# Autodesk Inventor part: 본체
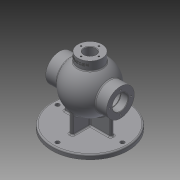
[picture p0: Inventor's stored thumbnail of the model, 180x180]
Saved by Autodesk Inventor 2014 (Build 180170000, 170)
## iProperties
Created: 2020-08
Part Number: 본체
Material: Generic
Document SubType Name: Modeling
Designer: kh
Density: 1 g/cm^3
Appearance: Default
Author: kh
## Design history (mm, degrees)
sketch "Sketch1"
  geometry: C1 r 85 at (0, 0); 1 further point
  constraints: 1 centre point, 1 coincident
  dimensions: "d0" = 170 diameter of C1
extrude "Extrusion1" new body sketch "Sketch1" distance "d1" = 10; taper "d2" = 0 deg
workplane "Work Plane1"
sketch "Sketch9"
  geometry: L1 (85, 10)-(-85, 10) reference; L2 (-85, 0)-(85, 0) reference; L3 (-76.651, 85)-(83.599, 85); L4 (-68, 116)-(-42.988, 116); L5 (42.988, 116)-(68, 116); L6 (-68, 102.5)-(-39.278, 102.5); L7 (39.278, 102.5)-(68, 102.5); L8 (68, 102.5)-(68, 116); L9 (-68, 102.5)-(-68, 116); L10 (0, 0)-(0, 85); A1 r 53 centre (0, 85) between (42.988, 116) and (-42.988, 116); A2 r 43 centre (0, 85) between (39.278, 102.5) and (-39.278, 102.5)
  constraints: 16 end point, 4 point on circle, 2 centre point, 2 coincident, 2 collinear, 2 parallel, 2 point on line, 2 vertical, 1 horizontal, 1 perpendicular, 1 other
  dimensions: "d72" = 85 distance from line of L2 L3.end; "d73" = 35 diameter of L6 L3; "d74" = 62 diameter of L4 L3; "d75" = 35 diameter of L7 L3; "d76" = 53 radius of A1; "d77" = 43 radius of A2; "d78" = 136 distance between parallel lines of L8 L9
revolve "Revolution2" sketch "Sketch9" stored, may be unused: angle "d79" = 90 deg
sketch "Sketch10"
  geometry: L1 (0, 0)-(0, 43); L2 (0, 43)-(-4, 43); L3 (-4, 43)-(-4, -43); L4 (-4, -43)-(4, -43); L5 (4, -43)-(4, 43); L6 (4, 43)-(0, 43); L7 (0, 0)-(-54, 0); L8 (-54, 0)-(-54, 4); L9 (-54, 4)-(50, 4); L10 (50, 4)-(50, -4); L11 (50, -4)-(-54, -4); L12 (-54, -4)-(-54, 0); C1 r 85 at (0, 0) reference; 1 further point
  constraints: 24 end point, 7 parallel, 2 perpendicular, 1 vertical
  dimensions: "d80" = 43 distance of L1.start L1.end; "d81" = 4 distance of L1.end L2.end; "d82" = 86 distance of L2.end L3.end; "d83" = 8 distance of L3.end L4.end; "d84" = 86 distance of L4.end L5.end; "d85" = 54 distance of L1.start L7.end; "d86" = 4 distance of L7.end L8.end; "d87" = 104 distance of L8.end L9.end; "d88" = 8 distance of L9.end L10.end; "d89" = 104 distance of L10.end L11.end
extrude "Extrusion7" join sketch "Sketch10" stored distance "d90" = 20; taper "d91" = 0 deg
workplane "Work Plane2"
sketch "Sketch11"
  geometry: C1 r 27 at (0, 0); 1 further point
  constraints: 1 centre point, 1 coincident
  dimensions: "d93" = 54 diameter of C1
extrude "Extrusion8" join sketch "Sketch11" stored distance "d94" = 20; taper "d95" = 0 deg
sketch "Sketch12" dims "d96" = 48
  geometry: L1 (0, 0)-(24, 0); C1 r 17.5 at (0, 0) reference; C2 r 31 at (0, 0) reference; 2 further points
  constraints: 2 coincident, 2 end point, 1 horizontal, 1 horizontal alignment, 2 other
hole "Hole1" sketch "Sketch12" at (24, 0) diameter "d97" = 3.459; stored, may be unused: countersink angle "d101" = 90 deg, drill point angle "d103" = 118 deg; dims "d98" = 12, "d99" = 4, "d100" = 2, "d102" = 15
pattern_circular "Circular Pattern1" dims angle "d105" = 360 deg
sketch "Sketch13" dims "d107" = 48
  geometry: L1 (0, 0)-(-24, 0); C1 r 31 at (0, 0) reference; C2 r 17.5 at (0, 0) reference; 2 further points
  constraints: 2 coincident, 2 end point, 1 horizontal, 1 horizontal alignment, 2 other
hole "Hole2" sketch "Sketch13" at (-24, 0) diameter "d108" = 3.459; stored, may be unused: countersink angle "d112" = 90 deg, drill point angle "d114" = 118 deg; dims "d109" = 12, "d110" = 4, "d111" = 2, "d113" = 15
pattern_circular "Circular Pattern2" dims angle "d116" = 360 deg
sketch "Sketch14"
  geometry: C1 r 27 at (0, 0) reference; C2 r 13 at (0, 0); 1 further point
  constraints: 1 centre point, 1 coincident
  dimensions: "d118" = 26 diameter of C2
extrude "Extrusion9" cut sketch "Sketch14" stored distance "d119" = 20; taper "d120" = 0 deg
sketch "Sketch15" dims "d121" = 40
  geometry: L1 (0, 0)-(0, 20); C1 r 13 at (0, 0) reference; C2 r 27 at (0, 0) reference; 2 further points
  constraints: 2 coincident, 2 end point, 1 vertical, 1 vertical alignment, 2 other
hole "Hole3" sketch "Sketch15" at (0, 20) diameter "d122" = 3.459; stored, may be unused: countersink angle "d126" = 90 deg, drill point angle "d128" = 118 deg; dims "d123" = 12, "d124" = 4, "d125" = 2, "d127" = 15
pattern_circular "Circular Pattern3" dims angle "d130" = 360 deg
sketch "Sketch16"
  geometry: L1 (0, 72.5)-(0, -72.5); L2 (-72.5, 0)-(72.5, 0); C1 r 85 at (0, 0) reference; A1 r 72.5 centre (0, 0) between (0, 72.5) and (0, -72.5); 7 further points
  constraints: 5 coincident, 4 end point, 4 midpoint, 4 point on circle, 1 centre point, 1 perpendicular, 1 vertical
  dimensions: "d132" = 145 diameter of A1
hole "Hole4" sketch "Sketch16" at (0, 72.5), (72.5, 0), (0, -72.5), (-72.5, 0) diameter "d133" = 9; stored, may be unused: countersink angle "d137" = 90 deg, drill point angle "d139" = 118 deg; dims "d134" = 12, "d135" = 4, "d136" = 2, "d138" = 15
sketch "Sketch17"
  geometry: L1 (-68, 67.5)-(-68, 102.5) reference; L2 (68, 67.5)-(68, 102.5) reference; L3 (-68, 85)-(68, 85); L4 (-39.278, 102.5)-(-68, 102.5) reference; L5 (-39.278, 67.5)-(-68, 67.5) reference; L6 (-52, 85)-(-52, 85); L7 (-52, 85)-(-52, 103.5); L8 (-52, 103.5)-(-50.25, 103.5); L9 (-50.25, 103.5)-(-50.25, 85); L10 (-52, 85)-(-50.25, 85); 1 further point
  constraints: 12 end point, 4 point on line, 3 perpendicular, 2 collinear, 2 midpoint
  dimensions: "d143" = 16 distance between parallel lines of L7 L1; "d144" = 37 diameter of L8 L3; "d145" = 1.75 distance of L7.end L8.end
revolve "Revolution3" sketch "Sketch17" stored, may be unused: angle "d146" = 90 deg
chamfer "Chamfer1" distance "d147" = 1; stored, may be unused: second distance "d148" = 2, angle "d149" = 45 deg
fillet "Fillet1" dims "d150" = 3
fillet "Fillet2" dims "d151" = 3
fillet "Fillet3" dims "d152" = 3
fillet "Fillet4" dims "d153" = 3
fillet "Fillet5" dims "d154" = 3
workplane "Work Plane3"
sketch "Sketch18"
  geometry: L1 (-20.739, -4.998)-(20.739, -4.998); L2 (20.739, -4.998)-(20.739, -11.002); L3 (20.739, -11.002)-(-20.739, -11.002); L4 (-20.739, -11.002)-(-20.739, -4.998); L5 (20.739, -4.998)-(-20.739, -11.002); L6 (-27, 0)-(27, 0) reference; L7 (27, 0)-(27, -17.714) reference; 2 further points
  constraints: 2 end point, 1 midpoint, 2 other
  dimensions: "d155" = 8 distance from line of point (0, -8) L6; "d156" = 27 distance from line of point (0, -8) L7
emboss "Emboss1" sketch "Sketch18" dims "d157" = 0.5, "d158" = 0
body "Solid1"
node "Projected Loop7"
node "Projected Loop8"
node "Projected Loop9"
node "Projected Loop10"
node "Projected Loop11"
node "Projected Loop12"
node "Projected Loop13"
